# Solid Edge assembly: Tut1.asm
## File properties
Author: CADCIM
Template: ansi assembly.asm
Last saved by: CADCIM
Revision: 5
Application: Solid Edge
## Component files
support_roller_bracket.par
stock_support_roller.par
adjusting_nut_handle.par
adjusting_screw_guide.par
Stock_support_base.par
thrust_bearing.par
adjusting_screw_nut.par
support_adjusting_screw.par
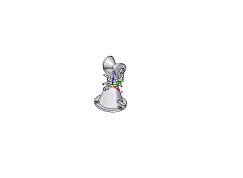
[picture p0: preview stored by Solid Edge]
